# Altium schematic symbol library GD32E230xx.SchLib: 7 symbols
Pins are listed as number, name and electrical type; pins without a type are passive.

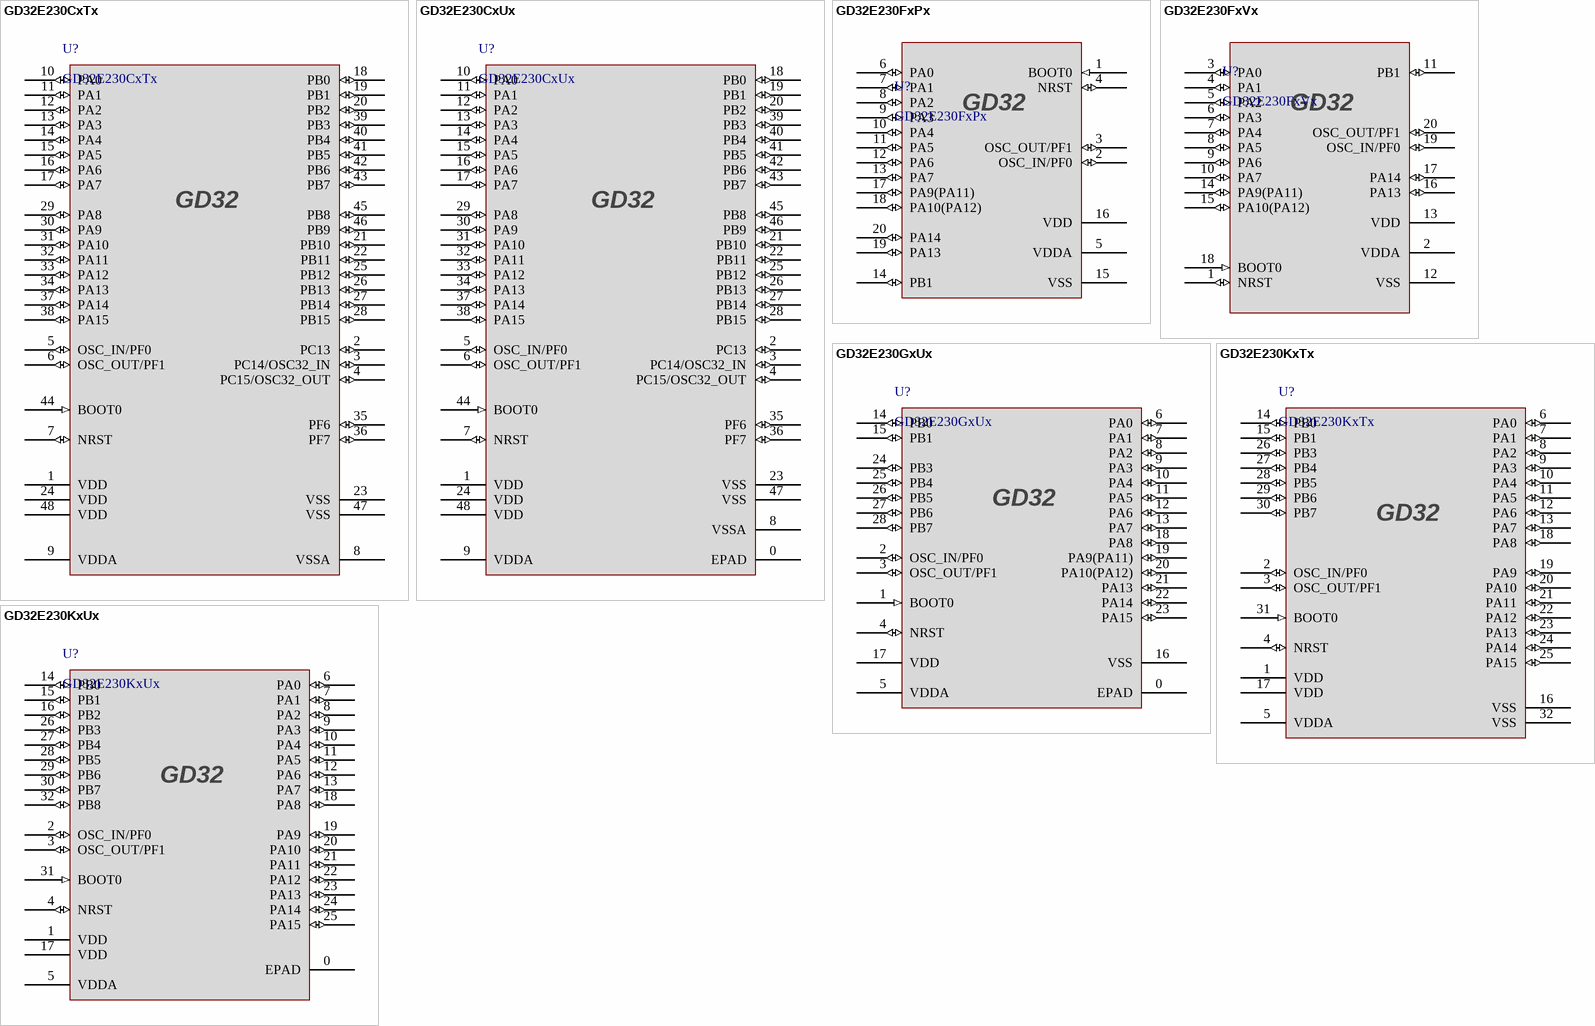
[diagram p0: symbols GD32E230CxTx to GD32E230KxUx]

## GD32E230CxTx
designator U?
footprint LQFP48_7x7x1.6
pins: 1 VDD (power), 2 PC13 (io), 3 PC14/OSC32_IN (io), 4 PC15/OSC32_OUT (io), 5 OSC_IN/PF0 (io), 6 OSC_OUT/PF1 (io), 7 NRST (io), 8 VSSA (power), 9 VDDA (power), 10 PA0 (io), 11 PA1 (io), 12 PA2 (io), 13 PA3 (io), 14 PA4 (io), 15 PA5 (io), 16 PA6 (io), 17 PA7 (io), 18 PB0 (io), 19 PB1 (io), 20 PB2 (io), 21 PB10 (io), 22 PB11 (io), 23 VSS (power), 24 VDD (power), 25 PB12 (io), 26 PB13 (io), 27 PB14 (io), 28 PB15 (io), 29 PA8 (io), 30 PA9 (io), 31 PA10 (io), 32 PA11 (io), 33 PA12 (io), 34 PA13 (io), 35 PF6 (io), 36 PF7 (io), 37 PA14 (io), 38 PA15 (io), 39 PB3 (io), 40 PB4 (io), 41 PB5 (io), 42 PB6 (io), 43 PB7 (io), 44 BOOT0 (in), 45 PB8 (io), 46 PB9 (io), 47 VSS (power), 48 VDD (power)

## GD32E230CxUx
designator U?
footprint QFN48_7X7X0.6
pins: 0 EPAD (power), 1 VDD (power), 2 PC13 (io), 3 PC14/OSC32_IN (io), 4 PC15/OSC32_OUT (io), 5 OSC_IN/PF0 (io), 6 OSC_OUT/PF1 (io), 7 NRST (io), 8 VSSA (power), 9 VDDA (power), 10 PA0 (io), 11 PA1 (io), 12 PA2 (io), 13 PA3 (io), 14 PA4 (io), 15 PA5 (io), 16 PA6 (io), 17 PA7 (io), 18 PB0 (io), 19 PB1 (io), 20 PB2 (io), 21 PB10 (io), 22 PB11 (io), 23 VSS (power), 24 VDD (power), 25 PB12 (io), 26 PB13 (io), 27 PB14 (io), 28 PB15 (io), 29 PA8 (io), 30 PA9 (io), 31 PA10 (io), 32 PA11 (io), 33 PA12 (io), 34 PA13 (io), 35 PF6 (io), 36 PF7 (io), 37 PA14 (io), 38 PA15 (io), 39 PB3 (io), 40 PB4 (io), 41 PB5 (io), 42 PB6 (io), 43 PB7 (io), 44 BOOT0 (in), 45 PB8 (io), 46 PB9 (io), 47 VSS (power), 48 VDD (power)

## GD32E230FxPx
designator U?
footprint TSSOP20-4.5x6.6x1.2
pins: 1 BOOT0 (in), 2 OSC_IN/PF0 (io), 3 OSC_OUT/PF1 (io), 4 NRST (io), 5 VDDA (power), 6 PA0 (io), 7 PA1 (io), 8 PA2 (io), 9 PA3 (io), 10 PA4 (io), 11 PA5 (io), 12 PA6 (io), 13 PA7 (io), 14 PB1 (io), 15 VSS (power), 16 VDD (power), 17 PA9(PA11) (io), 18 PA10(PA12) (io), 19 PA13 (io), 20 PA14 (io)

## GD32E230FxVx
designator U?
footprint LGA20_3x3X0.61
pins: 1 NRST (io), 2 VDDA (power), 3 PA0 (io), 4 PA1 (io), 5 PA2 (io), 6 PA3 (io), 7 PA4 (io), 8 PA5 (io), 9 PA6 (io), 10 PA7 (io), 11 PB1 (io), 12 VSS (power), 13 VDD (power), 14 PA9(PA11) (io), 15 PA10(PA12) (io), 16 PA13 (io), 17 PA14 (io), 18 BOOT0 (in), 19 OSC_IN/PF0 (io), 20 OSC_OUT/PF1 (io)

## GD32E230GxUx
designator U?
footprint QFN28_4X4X0.8
pins: 0 EPAD (power), 1 BOOT0 (in), 2 OSC_IN/PF0 (io), 3 OSC_OUT/PF1 (io), 4 NRST (io), 5 VDDA (power), 6 PA0 (io), 7 PA1 (io), 8 PA2 (io), 9 PA3 (io), 10 PA4 (io), 11 PA5 (io), 12 PA6 (io), 13 PA7 (io), 14 PB0 (io), 15 PB1 (io), 16 VSS (power), 17 VDD (power), 18 PA8 (io), 19 PA9(PA11) (io), 20 PA10(PA12) (io), 21 PA13 (io), 22 PA14 (io), 23 PA15 (io), 24 PB3 (io), 25 PB4 (io), 26 PB5 (io), 27 PB6 (io), 28 PB7 (io)

## GD32E230KxTx
designator U?
footprint LQFP32_7x7X1.6
pins: 1 VDD (power), 2 OSC_IN/PF0 (io), 3 OSC_OUT/PF1 (io), 4 NRST (io), 5 VDDA (power), 6 PA0 (io), 7 PA1 (io), 8 PA2 (io), 9 PA3 (io), 10 PA4 (io), 11 PA5 (io), 12 PA6 (io), 13 PA7 (io), 14 PB0 (io), 15 PB1 (io), 16 VSS (power), 17 VDD (power), 18 PA8 (io), 19 PA9 (io), 20 PA10 (io), 21 PA11 (io), 22 PA12 (io), 23 PA13 (io), 24 PA14 (io), 25 PA15 (io), 26 PB3 (io), 27 PB4 (io), 28 PB5 (io), 29 PB6 (io), 30 PB7 (io), 31 BOOT0 (in), 32 VSS (power)

## GD32E230KxUx
designator U?
footprint QFN32_5X5X0.8
pins: 0 EPAD (power), 1 VDD (power), 2 OSC_IN/PF0 (io), 3 OSC_OUT/PF1 (io), 4 NRST (io), 5 VDDA (power), 6 PA0 (io), 7 PA1 (io), 8 PA2 (io), 9 PA3 (io), 10 PA4 (io), 11 PA5 (io), 12 PA6 (io), 13 PA7 (io), 14 PB0 (io), 15 PB1 (io), 16 PB2 (io), 17 VDD (power), 18 PA8 (io), 19 PA9 (io), 20 PA10 (io), 21 PA11 (io), 22 PA12 (io), 23 PA13 (io), 24 PA14 (io), 25 PA15 (io), 26 PB3 (io), 27 PB4 (io), 28 PB5 (io), 29 PB6 (io), 30 PB7 (io), 31 BOOT0 (in), 32 PB8 (io)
